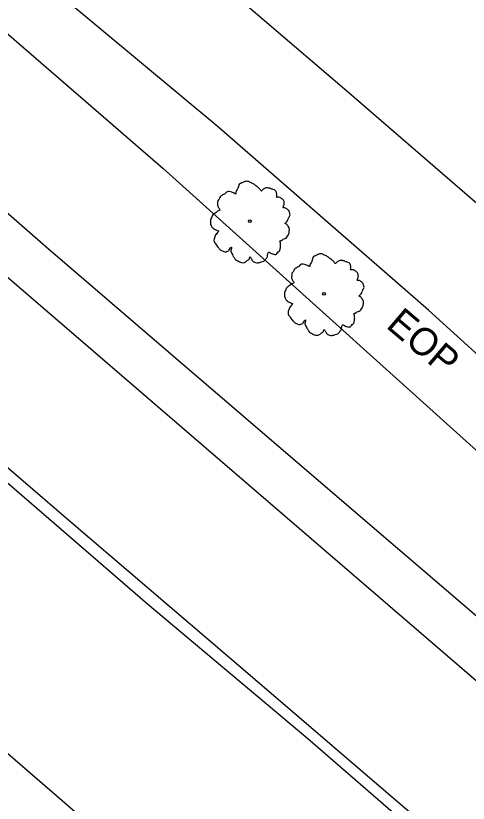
# Model space of a CAD drawing. Extents: x 2076109 to 2080761, y 592812 to 596750.
# Drawn here: x 2076996.8 to 2077078.6, y 596041.6 to 596184.1 of the extents above; entities that cross this region are included whole.
import ezdxf

# ---------------------------------------------------------------- set-up
doc = ezdxf.new("R2010")
doc.units = 0
for name, color, linetype in [('RD_EX_Fence_ChLk', 7, 'Continuous'), ('RD_EX_Misc', 7, 'Continuous'), ('RD_EX_Road', 7, 'Continuous'), ('RD_EX_Road_txCode', 7, 'Continuous'), ('RD_EX_VEG', 7, 'Continuous'), ('RD_HC_Cl', 7, 'Continuous')]:
    doc.layers.add(name, color=color, linetype=linetype)

msp = doc.modelspace()

# ---------------------------------------------------------------- linework, layer by layer
at = {"layer": 'RD_EX_Fence_ChLk'}
msp.add_lwpolyline([(2076822.97, 596329.73), (2076907.02, 596257.07), (2076948.27, 596221.63), (2077023.38, 596156.57), (2077092.73, 596094.04)], dxfattribs=at)
msp.add_lwpolyline([(2076822.97, 596329.73), (2076907.02, 596257.07), (2076948.27, 596221.63), (2077023.38, 596156.57), (2077092.73, 596094.04)], dxfattribs=at)
at = {"layer": 'RD_EX_Misc'}
for points in [[(2076810.47, 596295.64), (2076861.8, 596251.39), (2076900.57, 596218.06), (2076940.76, 596183.48), (2076983.39, 596147), (2077038.07, 596099.91), (2077086.97, 596057.78), (2077132.28, 596018.8), (2077181.85, 595976.05), (2077229.69, 595934.91), (2077274.19, 595896.66), (2077329.2, 595849.52), (2077358.6, 595824.22)], [(2076810.47, 596295.64), (2076861.8, 596251.39), (2076900.57, 596218.06), (2076940.76, 596183.48), (2076983.39, 596147), (2077038.07, 596099.91), (2077086.97, 596057.78), (2077132.28, 596018.8), (2077181.85, 595976.05), (2077229.69, 595934.91), (2077274.19, 595896.66), (2077329.2, 595849.52), (2077358.6, 595824.22)], [(2077334.93, 595810.96), (2077327.55, 595817.3), (2077300.53, 595840.37), (2077267.76, 595868.37), (2077240.07, 595892.05), (2077211.41, 595916.6), (2077178.43, 595944.97), (2077142.26, 595976.09), (2077108.47, 596005.28), (2077069.23, 596038.87), (2077039.16, 596064.68), (2077006.35, 596092.75), (2076967.21, 596126.45), (2076935.59, 596153.65), (2076905.14, 596179.73), (2076872.01, 596208.18), (2076841.3, 596234.65), (2076810.18, 596261.57), (2076792.25, 596277.09)], [(2077334.93, 595810.96), (2077327.55, 595817.3), (2077300.53, 595840.37), (2077267.76, 595868.37), (2077240.07, 595892.05), (2077211.41, 595916.6), (2077178.43, 595944.97), (2077142.26, 595976.09), (2077108.47, 596005.28), (2077069.23, 596038.87), (2077039.16, 596064.68), (2077006.35, 596092.75), (2076967.21, 596126.45), (2076935.59, 596153.65), (2076905.14, 596179.73), (2076872.01, 596208.18), (2076841.3, 596234.65), (2076810.18, 596261.57), (2076792.25, 596277.09)]]:
    msp.add_lwpolyline(points, dxfattribs=at)
at = {"layer": 'RD_EX_Road'}
for points in [[(2076842.97, 596352.71), (2076866.66, 596333.49), (2076894.56, 596310.65), (2076921.28, 596287.84), (2076946.98, 596265.34), (2076974.88, 596240.88), (2077000.65, 596218.69), (2077026.03, 596196.79), (2077056.62, 596170.55), (2077088.59, 596142.9), (2077102.76, 596132.06), (2077111.62, 596125.08), (2077125.62, 596114.47), (2077137.22, 596107.56), (2077155.37, 596096.64), (2077165.33, 596091.21), (2077183.91, 596082.52), (2077199.74, 596075.75), (2077216.78, 596070.63), (2077234.93, 596066.86), (2077254.14, 596063.85), (2077265.17, 596063.1), (2077275.23, 596063.54), (2077294.18, 596061.91)], [(2076842.97, 596352.71), (2076866.66, 596333.49), (2076894.56, 596310.65), (2076921.28, 596287.84), (2076946.98, 596265.34), (2076974.88, 596240.88), (2077000.65, 596218.69), (2077026.03, 596196.79), (2077056.62, 596170.55), (2077088.59, 596142.9), (2077102.76, 596132.06), (2077111.62, 596125.08), (2077125.62, 596114.47), (2077137.22, 596107.56), (2077155.37, 596096.64), (2077165.33, 596091.21), (2077183.91, 596082.52), (2077199.74, 596075.75), (2077216.78, 596070.63), (2077234.93, 596066.86), (2077254.14, 596063.85), (2077265.17, 596063.1), (2077275.23, 596063.54), (2077294.18, 596061.91)], [(2077310.8, 596045.6), (2077284.61, 596043.93), (2077263.73, 596044.86), (2077236.77, 596048.36), (2077217.91, 596052.27), (2077187.35, 596060.96), (2077164.2, 596069.76), (2077147.2, 596077.8), (2077123.41, 596090.88), (2077107.36, 596101.02), (2077085.71, 596117.86), (2077071.4, 596130.86), (2077033.15, 596164.21), (2077005.12, 596187.54), (2076967.19, 596220.06), (2076925.04, 596258.57), (2076895.71, 596284.71), (2076870.35, 596306.64), (2076830.55, 596340.86)], [(2077310.8, 596045.6), (2077284.61, 596043.93), (2077263.73, 596044.86), (2077236.77, 596048.36), (2077217.91, 596052.27), (2077187.35, 596060.96), (2077164.2, 596069.76), (2077147.2, 596077.8), (2077123.41, 596090.88), (2077107.36, 596101.02), (2077085.71, 596117.86), (2077071.4, 596130.86), (2077033.15, 596164.21), (2077005.12, 596187.54), (2076967.19, 596220.06), (2076925.04, 596258.57), (2076895.71, 596284.71), (2076870.35, 596306.64), (2076830.55, 596340.86)], [(2077309.59, 595877.22), (2077282.74, 595900.37), (2077256.36, 595923.26), (2077227.25, 595948.47), (2077198.79, 595972.87), (2077175.8, 595992.64), (2077153.37, 596012.36), (2077130.64, 596031.73), (2077105.62, 596053.51), (2077080.49, 596075.06), (2077051.54, 596099.91), (2077024.4, 596123.26), (2077002.19, 596142.32), (2076978.91, 596162.67), (2076952.21, 596185.24), (2076929.19, 596204.76), (2076902.69, 596227.39), (2076879.24, 596247.55), (2076859.1, 596264.86), (2076833.46, 596286.99), (2076816.41, 596301.99)], [(2077309.59, 595877.22), (2077282.74, 595900.37), (2077256.36, 595923.26), (2077227.25, 595948.47), (2077198.79, 595972.87), (2077175.8, 595992.64), (2077153.37, 596012.36), (2077130.64, 596031.73), (2077105.62, 596053.51), (2077080.49, 596075.06), (2077051.54, 596099.91), (2077024.4, 596123.26), (2077002.19, 596142.32), (2076978.91, 596162.67), (2076952.21, 596185.24), (2076929.19, 596204.76), (2076902.69, 596227.39), (2076879.24, 596247.55), (2076859.1, 596264.86), (2076833.46, 596286.99), (2076816.41, 596301.99)], [(2076790.96, 596275.94), (2076814.77, 596255.12), (2076842.21, 596231.47), (2076870.29, 596207.22), (2076894.79, 596186.02), (2076920.29, 596164.11), (2076947.36, 596141.05), (2076969.17, 596122), (2076994.72, 596100.04), (2077020.61, 596077.66), (2077049.58, 596053.31), (2077078.66, 596028.07), (2077094.19, 596014.5), (2077117.9, 595994.16), (2077143.78, 595971.83), (2077167.12, 595951.98), (2077186.93, 595934.87), (2077205.77, 595918.84), (2077227.43, 595900.11), (2077245.34, 595884.56), (2077262.98, 595869.29), (2077283.52, 595851.63), (2077302.45, 595835.44)], [(2076790.96, 596275.94), (2076814.77, 596255.12), (2076842.21, 596231.47), (2076870.29, 596207.22), (2076894.79, 596186.02), (2076920.29, 596164.11), (2076947.36, 596141.05), (2076969.17, 596122), (2076994.72, 596100.04), (2077020.61, 596077.66), (2077049.58, 596053.31), (2077078.66, 596028.07), (2077094.19, 596014.5), (2077117.9, 595994.16), (2077143.78, 595971.83), (2077167.12, 595951.98), (2077186.93, 595934.87), (2077205.77, 595918.84), (2077227.43, 595900.11), (2077245.34, 595884.56), (2077262.98, 595869.29), (2077283.52, 595851.63), (2077302.45, 595835.44)]]:
    msp.add_lwpolyline(points, dxfattribs=at)
at = {"layer": 'RD_EX_VEG'}
for centre, radius in [((2077039.11, 596146.95), 0.25), ((2077039.11, 596146.95), 0.25), ((2077039.09, 596146.95), 0.0001), ((2077039.09, 596146.95), 0.0001), ((2077052.51, 596133.8), 0.25), ((2077052.51, 596133.8), 0.25), ((2077052.48, 596133.8), 0.0001), ((2077052.48, 596133.8), 0.0001)]:
    msp.add_circle(centre, radius, dxfattribs=at)
for points in [[(2077043.86, 596152.33), (2077043.64, 596152.54), (2077043.33, 596152.68), (2077043.08, 596152.76), (2077042.86, 596152.85), (2077042.62, 596152.92), (2077042.28, 596152.98), (2077041.98, 596152.97), (2077041.72, 596152.86), (2077041.54, 596152.73), (2077041.32, 596152.55), (2077041.21, 596152.41), (2077041.1, 596152.48), (2077041, 596152.59), (2077040.86, 596152.81), (2077040.67, 596152.97), (2077040.48, 596153.14), (2077040.19, 596153.34), (2077039.93, 596153.57), (2077039.68, 596153.71), (2077039.4, 596153.88), (2077039.04, 596154.03), (2077038.69, 596154.16), (2077038.3, 596154.16), (2077037.8, 596153.97), (2077037.48, 596153.78), (2077037.2, 596153.69), (2077037.03, 596153.25), (2077036.93, 596152.87), (2077036.82, 596152.7), (2077036.61, 596152.33), (2077036.54, 596152.09), (2077036.5, 596151.86), (2077036.43, 596151.89), (2077036.11, 596152.09), (2077035.82, 596152.21), (2077035.35, 596152.31), (2077035.03, 596152.29), (2077034.74, 596152.1), (2077034.5, 596151.85), (2077034.29, 596151.77), (2077034.06, 596151.61), (2077033.99, 596151.56), (2077033.74, 596151.35), (2077033.53, 596150.94), (2077033.32, 596150.66), (2077033.27, 596150.41), (2077033.27, 596150.18), (2077033.24, 596149.87), (2077033.4, 596149.44), (2077033.58, 596149.16), (2077033.72, 596149.01), (2077033.26, 596148.74), (2077033, 596148.51), (2077032.64, 596148.28), (2077032.59, 596148.23), (2077032.25, 596147.9), (2077032.15, 596147.55), (2077031.97, 596147.22), (2077031.95, 596146.93), (2077031.97, 596146.53), (2077032.07, 596146.14), (2077032.37, 596145.73), (2077032.69, 596145.49), (2077033.24, 596145.25), (2077033.48, 596145.14), (2077033.35, 596145.02), (2077033.13, 596144.72), (2077032.85, 596144.4), (2077032.75, 596144.05), (2077032.65, 596143.78), (2077032.6, 596143.49), (2077032.71, 596143.11), (2077032.96, 596142.79), (2077033.19, 596142.41), (2077033.48, 596142.06), (2077033.85, 596141.71), (2077034.4, 596141.44), (2077034.69, 596141.36), (2077034.88, 596141.43), (2077035.28, 596141.58), (2077035.38, 596141.79), (2077035.79, 596142.23), (2077035.75, 596142.03), (2077035.66, 596141.65), (2077035.85, 596141.1), (2077036.04, 596140.7), (2077036.3, 596140.28), (2077036.48, 596140.03), (2077036.89, 596139.78), (2077037.23, 596139.59), (2077037.59, 596139.45), (2077038, 596139.46), (2077038.31, 596139.56), (2077038.53, 596139.74), (2077038.83, 596139.97), (2077038.98, 596140.07)], [(2077043.86, 596152.33), (2077043.64, 596152.54), (2077043.33, 596152.68), (2077043.08, 596152.76), (2077042.86, 596152.85), (2077042.62, 596152.92), (2077042.28, 596152.98), (2077041.98, 596152.97), (2077041.72, 596152.86), (2077041.54, 596152.73), (2077041.32, 596152.55), (2077041.21, 596152.41), (2077041.1, 596152.48), (2077041, 596152.59), (2077040.86, 596152.81), (2077040.67, 596152.97), (2077040.48, 596153.14), (2077040.19, 596153.34), (2077039.93, 596153.57), (2077039.68, 596153.71), (2077039.4, 596153.88), (2077039.04, 596154.03), (2077038.69, 596154.16), (2077038.3, 596154.16), (2077037.8, 596153.97), (2077037.48, 596153.78), (2077037.2, 596153.69), (2077037.03, 596153.25), (2077036.93, 596152.87), (2077036.82, 596152.7), (2077036.61, 596152.33), (2077036.54, 596152.09), (2077036.5, 596151.86), (2077036.43, 596151.89), (2077036.11, 596152.09), (2077035.82, 596152.21), (2077035.35, 596152.31), (2077035.03, 596152.29), (2077034.74, 596152.1), (2077034.5, 596151.85), (2077034.29, 596151.77), (2077034.06, 596151.61), (2077033.99, 596151.56), (2077033.74, 596151.35), (2077033.53, 596150.94), (2077033.32, 596150.66), (2077033.27, 596150.41), (2077033.27, 596150.18), (2077033.24, 596149.87), (2077033.4, 596149.44), (2077033.58, 596149.16), (2077033.72, 596149.01), (2077033.26, 596148.74), (2077033, 596148.51), (2077032.64, 596148.28), (2077032.59, 596148.23), (2077032.25, 596147.9), (2077032.15, 596147.55), (2077031.97, 596147.22), (2077031.95, 596146.93), (2077031.97, 596146.53), (2077032.07, 596146.14), (2077032.37, 596145.73), (2077032.69, 596145.49), (2077033.24, 596145.25), (2077033.48, 596145.14), (2077033.35, 596145.02), (2077033.13, 596144.72), (2077032.85, 596144.4), (2077032.75, 596144.05), (2077032.65, 596143.78), (2077032.6, 596143.49), (2077032.71, 596143.11), (2077032.96, 596142.79), (2077033.19, 596142.41), (2077033.48, 596142.06), (2077033.85, 596141.71), (2077034.4, 596141.44), (2077034.69, 596141.36), (2077034.88, 596141.43), (2077035.28, 596141.58), (2077035.38, 596141.79), (2077035.79, 596142.23), (2077035.75, 596142.03), (2077035.66, 596141.65), (2077035.85, 596141.1), (2077036.04, 596140.7), (2077036.3, 596140.28), (2077036.48, 596140.03), (2077036.89, 596139.78), (2077037.23, 596139.59), (2077037.59, 596139.45), (2077038, 596139.46), (2077038.31, 596139.56), (2077038.53, 596139.74), (2077038.83, 596139.97), (2077038.98, 596140.07)], [(2077038.98, 596140.07), (2077039.04, 596140.26), (2077039.16, 596140.48), (2077039.2, 596140.41), (2077039.3, 596140.26), (2077039.43, 596139.99), (2077039.55, 596139.78), (2077039.82, 596139.59), (2077040.09, 596139.49), (2077040.61, 596139.41), (2077041.13, 596139.59), (2077041.6, 596139.72), (2077041.86, 596139.92), (2077041.97, 596140.12), (2077042.28, 596140.52), (2077042.29, 596140.84), (2077042.33, 596140.96), (2077042.51, 596141.33), (2077042.6, 596141.32), (2077042.84, 596141.18), (2077043.21, 596141.04), (2077043.5, 596140.95), (2077043.78, 596140.94), (2077043.99, 596141.06), (2077044.23, 596141.38), (2077044.52, 596141.66), (2077044.56, 596141.82), (2077044.59, 596142), (2077044.66, 596142.2), (2077044.64, 596142.41), (2077044.66, 596142.59), (2077044.65, 596142.73), (2077044.65, 596142.93), (2077044.6, 596143.13), (2077044.52, 596143.27), (2077044.58, 596143.42), (2077044.82, 596143.47), (2077044.92, 596143.51), (2077045.09, 596143.67), (2077045.49, 596143.79), (2077045.78, 596144.06), (2077046.02, 596144.42), (2077046.16, 596144.66), (2077046.22, 596144.97), (2077046.23, 596145.29), (2077046.25, 596145.5), (2077046.2, 596145.71), (2077046.03, 596146.02), (2077045.88, 596146.22), (2077045.61, 596146.44), (2077045.49, 596146.61), (2077045.54, 596146.63), (2077045.64, 596146.75), (2077045.82, 596146.96), (2077046.05, 596147.35), (2077046.26, 596147.82), (2077046.28, 596147.84), (2077046.36, 596148.1), (2077046.32, 596148.4), (2077046.25, 596148.59), (2077046.18, 596148.81), (2077046.01, 596148.99), (2077045.78, 596149.19), (2077045.53, 596149.33), (2077045.32, 596149.38), (2077045.1, 596149.4), (2077045.14, 596149.56), (2077045.26, 596149.85), (2077045.32, 596150), (2077045.32, 596150.23), (2077045.28, 596150.53), (2077045.02, 596150.91), (2077044.49, 596151.26), (2077044.13, 596151.3), (2077043.91, 596151.27), (2077043.95, 596151.4), (2077043.93, 596151.68), (2077043.96, 596151.88), (2077043.91, 596152.08), (2077043.86, 596152.26), (2077043.82, 596152.36)], [(2077038.98, 596140.07), (2077039.04, 596140.26), (2077039.16, 596140.48), (2077039.2, 596140.41), (2077039.3, 596140.26), (2077039.43, 596139.99), (2077039.55, 596139.78), (2077039.82, 596139.59), (2077040.09, 596139.49), (2077040.61, 596139.41), (2077041.13, 596139.59), (2077041.6, 596139.72), (2077041.86, 596139.92), (2077041.97, 596140.12), (2077042.28, 596140.52), (2077042.29, 596140.84), (2077042.33, 596140.96), (2077042.51, 596141.33), (2077042.6, 596141.32), (2077042.84, 596141.18), (2077043.21, 596141.04), (2077043.5, 596140.95), (2077043.78, 596140.94), (2077043.99, 596141.06), (2077044.23, 596141.38), (2077044.52, 596141.66), (2077044.56, 596141.82), (2077044.59, 596142), (2077044.66, 596142.2), (2077044.64, 596142.41), (2077044.66, 596142.59), (2077044.65, 596142.73), (2077044.65, 596142.93), (2077044.6, 596143.13), (2077044.52, 596143.27), (2077044.58, 596143.42), (2077044.82, 596143.47), (2077044.92, 596143.51), (2077045.09, 596143.67), (2077045.49, 596143.79), (2077045.78, 596144.06), (2077046.02, 596144.42), (2077046.16, 596144.66), (2077046.22, 596144.97), (2077046.23, 596145.29), (2077046.25, 596145.5), (2077046.2, 596145.71), (2077046.03, 596146.02), (2077045.88, 596146.22), (2077045.61, 596146.44), (2077045.49, 596146.61), (2077045.54, 596146.63), (2077045.64, 596146.75), (2077045.82, 596146.96), (2077046.05, 596147.35), (2077046.26, 596147.82), (2077046.28, 596147.84), (2077046.36, 596148.1), (2077046.32, 596148.4), (2077046.25, 596148.59), (2077046.18, 596148.81), (2077046.01, 596148.99), (2077045.78, 596149.19), (2077045.53, 596149.33), (2077045.32, 596149.38), (2077045.1, 596149.4), (2077045.14, 596149.56), (2077045.26, 596149.85), (2077045.32, 596150), (2077045.32, 596150.23), (2077045.28, 596150.53), (2077045.02, 596150.91), (2077044.49, 596151.26), (2077044.13, 596151.3), (2077043.91, 596151.27), (2077043.95, 596151.4), (2077043.93, 596151.68), (2077043.96, 596151.88), (2077043.91, 596152.08), (2077043.86, 596152.26), (2077043.82, 596152.36)], [(2077057.25, 596139.18), (2077057.04, 596139.39), (2077056.72, 596139.53), (2077056.47, 596139.61), (2077056.25, 596139.7), (2077056.01, 596139.77), (2077055.67, 596139.83), (2077055.37, 596139.82), (2077055.11, 596139.71), (2077054.93, 596139.58), (2077054.71, 596139.4), (2077054.6, 596139.27), (2077054.49, 596139.33), (2077054.39, 596139.44), (2077054.25, 596139.66), (2077054.06, 596139.82), (2077053.87, 596139.99), (2077053.59, 596140.19), (2077053.32, 596140.42), (2077053.08, 596140.56), (2077052.8, 596140.73), (2077052.43, 596140.88), (2077052.08, 596141.01), (2077051.69, 596141.02), (2077051.2, 596140.82), (2077050.87, 596140.63), (2077050.6, 596140.54), (2077050.42, 596140.1), (2077050.33, 596139.72), (2077050.22, 596139.55), (2077050, 596139.18), (2077049.93, 596138.94), (2077049.89, 596138.71), (2077049.82, 596138.74), (2077049.5, 596138.94), (2077049.21, 596139.06), (2077048.74, 596139.16), (2077048.42, 596139.14), (2077048.14, 596138.96), (2077047.89, 596138.7), (2077047.69, 596138.62), (2077047.45, 596138.46), (2077047.38, 596138.42), (2077047.13, 596138.2), (2077046.92, 596137.79), (2077046.71, 596137.51), (2077046.66, 596137.26), (2077046.66, 596137.03), (2077046.63, 596136.72), (2077046.79, 596136.29), (2077046.98, 596136.01), (2077047.11, 596135.86), (2077046.65, 596135.59), (2077046.39, 596135.36), (2077046.04, 596135.13), (2077045.99, 596135.08), (2077045.64, 596134.75), (2077045.55, 596134.4), (2077045.36, 596134.07), (2077045.35, 596133.78), (2077045.36, 596133.38), (2077045.46, 596132.99), (2077045.76, 596132.58), (2077046.09, 596132.34), (2077046.64, 596132.1), (2077046.88, 596131.99), (2077046.74, 596131.88), (2077046.52, 596131.57), (2077046.24, 596131.25), (2077046.15, 596130.91), (2077046.05, 596130.63), (2077046, 596130.34), (2077046.1, 596129.96), (2077046.36, 596129.65), (2077046.58, 596129.26), (2077046.88, 596128.91), (2077047.24, 596128.56), (2077047.8, 596128.29), (2077048.09, 596128.21), (2077048.28, 596128.28), (2077048.67, 596128.43), (2077048.78, 596128.64), (2077049.19, 596129.08), (2077049.15, 596128.88), (2077049.05, 596128.5), (2077049.24, 596127.95), (2077049.43, 596127.55), (2077049.7, 596127.13), (2077049.88, 596126.88), (2077050.29, 596126.63), (2077050.62, 596126.45), (2077050.99, 596126.3), (2077051.39, 596126.31), (2077051.71, 596126.41), (2077051.92, 596126.59), (2077052.22, 596126.82), (2077052.37, 596126.92)], [(2077057.25, 596139.18), (2077057.04, 596139.39), (2077056.72, 596139.53), (2077056.47, 596139.61), (2077056.25, 596139.7), (2077056.01, 596139.77), (2077055.67, 596139.83), (2077055.37, 596139.82), (2077055.11, 596139.71), (2077054.93, 596139.58), (2077054.71, 596139.4), (2077054.6, 596139.27), (2077054.49, 596139.33), (2077054.39, 596139.44), (2077054.25, 596139.66), (2077054.06, 596139.82), (2077053.87, 596139.99), (2077053.59, 596140.19), (2077053.32, 596140.42), (2077053.08, 596140.56), (2077052.8, 596140.73), (2077052.43, 596140.88), (2077052.08, 596141.01), (2077051.69, 596141.02), (2077051.2, 596140.82), (2077050.87, 596140.63), (2077050.6, 596140.54), (2077050.42, 596140.1), (2077050.33, 596139.72), (2077050.22, 596139.55), (2077050, 596139.18), (2077049.93, 596138.94), (2077049.89, 596138.71), (2077049.82, 596138.74), (2077049.5, 596138.94), (2077049.21, 596139.06), (2077048.74, 596139.16), (2077048.42, 596139.14), (2077048.14, 596138.96), (2077047.89, 596138.7), (2077047.69, 596138.62), (2077047.45, 596138.46), (2077047.38, 596138.42), (2077047.13, 596138.2), (2077046.92, 596137.79), (2077046.71, 596137.51), (2077046.66, 596137.26), (2077046.66, 596137.03), (2077046.63, 596136.72), (2077046.79, 596136.29), (2077046.98, 596136.01), (2077047.11, 596135.86), (2077046.65, 596135.59), (2077046.39, 596135.36), (2077046.04, 596135.13), (2077045.99, 596135.08), (2077045.64, 596134.75), (2077045.55, 596134.4), (2077045.36, 596134.07), (2077045.35, 596133.78), (2077045.36, 596133.38), (2077045.46, 596132.99), (2077045.76, 596132.58), (2077046.09, 596132.34), (2077046.64, 596132.1), (2077046.88, 596131.99), (2077046.74, 596131.88), (2077046.52, 596131.57), (2077046.24, 596131.25), (2077046.15, 596130.91), (2077046.05, 596130.63), (2077046, 596130.34), (2077046.1, 596129.96), (2077046.36, 596129.65), (2077046.58, 596129.26), (2077046.88, 596128.91), (2077047.24, 596128.56), (2077047.8, 596128.29), (2077048.09, 596128.21), (2077048.28, 596128.28), (2077048.67, 596128.43), (2077048.78, 596128.64), (2077049.19, 596129.08), (2077049.15, 596128.88), (2077049.05, 596128.5), (2077049.24, 596127.95), (2077049.43, 596127.55), (2077049.7, 596127.13), (2077049.88, 596126.88), (2077050.29, 596126.63), (2077050.62, 596126.45), (2077050.99, 596126.3), (2077051.39, 596126.31), (2077051.71, 596126.41), (2077051.92, 596126.59), (2077052.22, 596126.82), (2077052.37, 596126.92)], [(2077052.37, 596126.92), (2077052.43, 596127.11), (2077052.55, 596127.33), (2077052.59, 596127.26), (2077052.69, 596127.11), (2077052.82, 596126.84), (2077052.95, 596126.63), (2077053.21, 596126.44), (2077053.48, 596126.34), (2077054, 596126.26), (2077054.52, 596126.44), (2077054.99, 596126.57), (2077055.26, 596126.77), (2077055.37, 596126.97), (2077055.67, 596127.37), (2077055.68, 596127.69), (2077055.72, 596127.82), (2077055.91, 596128.18), (2077055.99, 596128.17), (2077056.24, 596128.03), (2077056.6, 596127.89), (2077056.89, 596127.8), (2077057.18, 596127.79), (2077057.38, 596127.91), (2077057.62, 596128.24), (2077057.92, 596128.51), (2077057.96, 596128.67), (2077057.98, 596128.85), (2077058.05, 596129.05), (2077058.03, 596129.26), (2077058.06, 596129.44), (2077058.04, 596129.58), (2077058.05, 596129.78), (2077057.99, 596129.98), (2077057.91, 596130.12), (2077057.97, 596130.27), (2077058.21, 596130.32), (2077058.32, 596130.37), (2077058.48, 596130.52), (2077058.88, 596130.64), (2077059.18, 596130.91), (2077059.41, 596131.27), (2077059.55, 596131.51), (2077059.62, 596131.82), (2077059.63, 596132.14), (2077059.65, 596132.35), (2077059.59, 596132.56), (2077059.43, 596132.87), (2077059.27, 596133.07), (2077059, 596133.29), (2077058.88, 596133.46), (2077058.93, 596133.48), (2077059.03, 596133.6), (2077059.21, 596133.81), (2077059.44, 596134.2), (2077059.65, 596134.68), (2077059.67, 596134.69), (2077059.75, 596134.95), (2077059.71, 596135.25), (2077059.64, 596135.44), (2077059.57, 596135.66), (2077059.4, 596135.84), (2077059.17, 596136.04), (2077058.93, 596136.18), (2077058.71, 596136.23), (2077058.5, 596136.25), (2077058.54, 596136.41), (2077058.65, 596136.7), (2077058.71, 596136.85), (2077058.71, 596137.08), (2077058.67, 596137.38), (2077058.41, 596137.77), (2077057.89, 596138.11), (2077057.53, 596138.16), (2077057.3, 596138.12), (2077057.34, 596138.25), (2077057.32, 596138.53), (2077057.36, 596138.73), (2077057.3, 596138.93), (2077057.25, 596139.11), (2077057.21, 596139.21)], [(2077052.37, 596126.92), (2077052.43, 596127.11), (2077052.55, 596127.33), (2077052.59, 596127.26), (2077052.69, 596127.11), (2077052.82, 596126.84), (2077052.95, 596126.63), (2077053.21, 596126.44), (2077053.48, 596126.34), (2077054, 596126.26), (2077054.52, 596126.44), (2077054.99, 596126.57), (2077055.26, 596126.77), (2077055.37, 596126.97), (2077055.67, 596127.37), (2077055.68, 596127.69), (2077055.72, 596127.82), (2077055.91, 596128.18), (2077055.99, 596128.17), (2077056.24, 596128.03), (2077056.6, 596127.89), (2077056.89, 596127.8), (2077057.18, 596127.79), (2077057.38, 596127.91), (2077057.62, 596128.24), (2077057.92, 596128.51), (2077057.96, 596128.67), (2077057.98, 596128.85), (2077058.05, 596129.05), (2077058.03, 596129.26), (2077058.06, 596129.44), (2077058.04, 596129.58), (2077058.05, 596129.78), (2077057.99, 596129.98), (2077057.91, 596130.12), (2077057.97, 596130.27), (2077058.21, 596130.32), (2077058.32, 596130.37), (2077058.48, 596130.52), (2077058.88, 596130.64), (2077059.18, 596130.91), (2077059.41, 596131.27), (2077059.55, 596131.51), (2077059.62, 596131.82), (2077059.63, 596132.14), (2077059.65, 596132.35), (2077059.59, 596132.56), (2077059.43, 596132.87), (2077059.27, 596133.07), (2077059, 596133.29), (2077058.88, 596133.46), (2077058.93, 596133.48), (2077059.03, 596133.6), (2077059.21, 596133.81), (2077059.44, 596134.2), (2077059.65, 596134.68), (2077059.67, 596134.69), (2077059.75, 596134.95), (2077059.71, 596135.25), (2077059.64, 596135.44), (2077059.57, 596135.66), (2077059.4, 596135.84), (2077059.17, 596136.04), (2077058.93, 596136.18), (2077058.71, 596136.23), (2077058.5, 596136.25), (2077058.54, 596136.41), (2077058.65, 596136.7), (2077058.71, 596136.85), (2077058.71, 596137.08), (2077058.67, 596137.38), (2077058.41, 596137.77), (2077057.89, 596138.11), (2077057.53, 596138.16), (2077057.3, 596138.12), (2077057.34, 596138.25), (2077057.32, 596138.53), (2077057.36, 596138.73), (2077057.3, 596138.93), (2077057.25, 596139.11), (2077057.21, 596139.21)]]:
    msp.add_spline(points, degree=3, dxfattribs=at)
at = {"layer": 'RD_HC_Cl'}
msp.add_line((2076186.59, 596746.26), (2077404.89, 595698.18), dxfattribs=at)

# ---------------------------------------------------------------- texts
at = {"layer": 'RD_EX_Road_txCode'}
msp.add_text('EOP', height=5, rotation=319.6274, dxfattribs=at).set_placement((2077063.54, 596127.81))
msp.add_text('EOP', height=5, rotation=319.6274, dxfattribs=at).set_placement((2077063.54, 596127.81))

doc.saveas('drawing.dxf')
